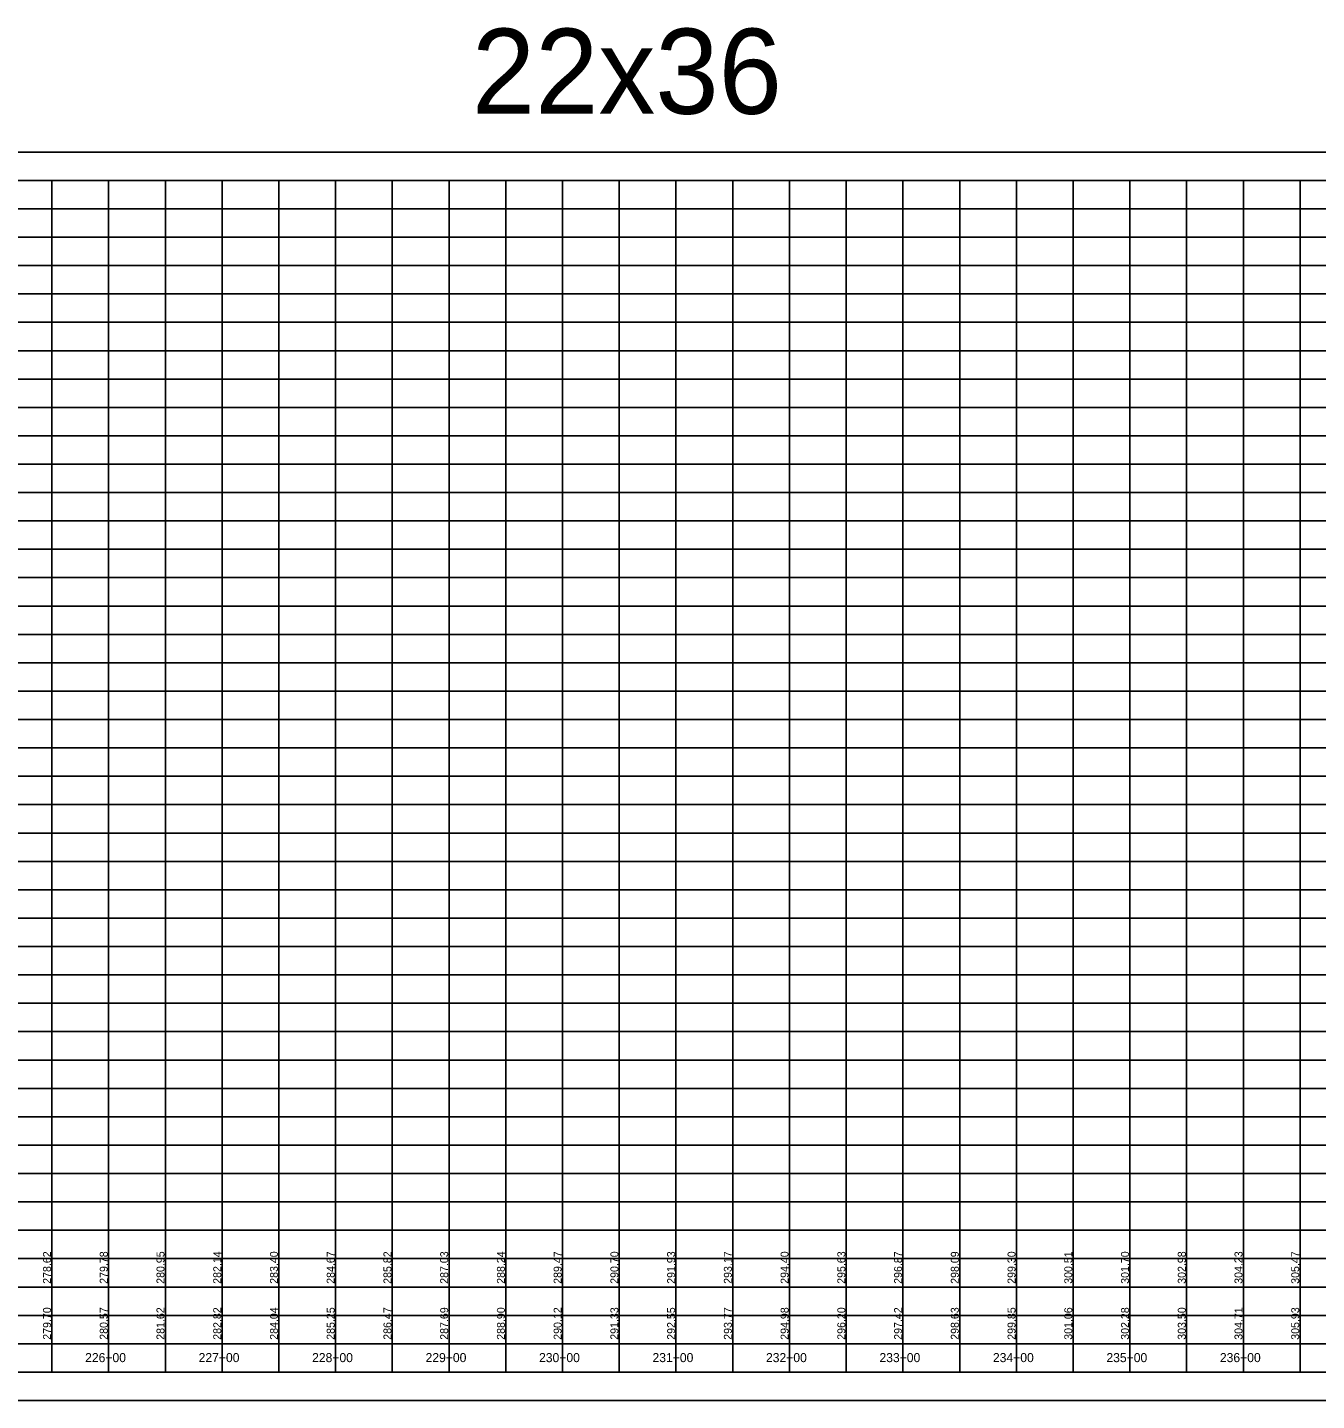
# Model space of a CAD drawing. Extents: x 1873632 to 1926512, y 813126 to 836257.
# Drawn here: x 1900891 to 1902027, y 831005 to 832214 of the extents above; entities that cross this region are included whole.
import ezdxf

# ---------------------------------------------------------------- set-up
doc = ezdxf.new("R2010")
doc.units = 0
for name, color, linetype in [('RD_DDB_StaTX', 7, 'Continuous'), ('RD_DDB_StripGrade', 7, 'Continuous'), ('RD_PD_WallFill', 7, 'Continuous'), ('RD_SHT_IplotShp', 7, 'Continuous')]:
    doc.layers.add(name, color=color, linetype=linetype)

msp = doc.modelspace()

# ---------------------------------------------------------------- linework, layer by layer
at = {"layer": 'RD_PD_WallFill'}
for p, q in [((1899712.9, 832079.6), (1905062.9, 832079.6)), ((1899712.9, 832079.6), (1901462.9, 832079.6)), ((1900912.9, 831029.6), (1900912.9, 832079.6)), ((1900912.9, 831029.6), (1900912.9, 832079.6)), ((1900962.9, 831029.6), (1900962.9, 832079.6)), ((1900962.9, 831029.6), (1900962.9, 832079.6)), ((1901012.9, 831029.6), (1901012.9, 832079.6)), ((1901012.9, 831029.6), (1901012.9, 832079.6)), ((1901062.9, 831029.6), (1901062.9, 832079.6)), ((1901062.9, 831029.6), (1901062.9, 832079.6)), ((1901112.9, 831029.6), (1901112.9, 832079.6)), ((1901112.9, 831029.6), (1901112.9, 832079.6)), ((1901162.9, 831029.6), (1901162.9, 832079.6)), ((1901162.9, 831029.6), (1901162.9, 832079.6)), ((1901212.9, 831029.6), (1901212.9, 832079.6)), ((1901212.9, 831029.6), (1901212.9, 832079.6)), ((1901262.9, 831029.6), (1901262.9, 832079.6)), ((1901262.9, 831029.6), (1901262.9, 832079.6)), ((1901312.9, 831029.6), (1901312.9, 832079.6)), ((1901312.9, 831029.6), (1901312.9, 832079.6)), ((1901362.9, 831029.6), (1901362.9, 832079.6)), ((1901362.9, 831029.6), (1901362.9, 832079.6)), ((1901412.9, 831029.6), (1901412.9, 832079.6)), ((1901412.9, 831029.6), (1901412.9, 832079.6)), ((1901462.9, 831029.6), (1901462.9, 832079.6)), ((1901462.9, 831029.6), (1901462.9, 832079.6)), ((1901512.9, 831029.6), (1901512.9, 832079.6)), ((1901512.9, 831029.6), (1901512.9, 832079.6)), ((1901562.9, 831029.6), (1901562.9, 832079.6)), ((1901562.9, 831029.6), (1901562.9, 832079.6)), ((1901612.9, 831029.6), (1901612.9, 832079.6)), ((1901612.9, 831029.6), (1901612.9, 832079.6)), ((1901662.9, 831029.6), (1901662.9, 832079.6)), ((1901662.9, 831029.6), (1901662.9, 832079.6)), ((1901712.9, 831029.6), (1901712.9, 832079.6)), ((1901712.9, 831029.6), (1901712.9, 832079.6)), ((1901762.9, 831029.6), (1901762.9, 832079.6)), ((1901762.9, 831029.6), (1901762.9, 832079.6)), ((1901812.9, 831029.6), (1901812.9, 832079.6)), ((1901812.9, 831029.6), (1901812.9, 832079.6)), ((1901862.9, 831029.6), (1901862.9, 832079.6)), ((1901862.9, 831029.6), (1901862.9, 832079.6)), ((1901912.9, 831029.6), (1901912.9, 832079.6)), ((1901912.9, 831029.6), (1901912.9, 832079.6)), ((1901962.9, 831029.6), (1901962.9, 832079.6)), ((1901962.9, 831029.6), (1901962.9, 832079.6)), ((1902012.9, 831029.6), (1902012.9, 832079.6)), ((1902012.9, 831029.6), (1902012.9, 832079.6)), ((1900162.9, 832054.6), (1905062.9, 832054.6)), ((1900162.9, 832054.6), (1905062.9, 832054.6)), ((1900162.9, 832029.6), (1905062.9, 832029.6)), ((1900162.9, 832004.6), (1905062.9, 832004.6)), ((1900162.9, 831979.6), (1905062.9, 831979.6)), ((1900162.9, 831954.6), (1905062.9, 831954.6)), ((1899712.9, 831929.6), (1905062.9, 831929.6)), ((1899712.9, 831904.6), (1905062.9, 831904.6)), ((1899712.9, 831879.6), (1905062.9, 831879.6)), ((1899712.9, 831854.6), (1905062.9, 831854.6)), ((1899712.9, 831829.6), (1905062.9, 831829.6)), ((1899712.9, 831804.6), (1905062.9, 831804.6)), ((1899712.9, 831779.6), (1905062.9, 831779.6)), ((1899712.9, 831754.6), (1905062.9, 831754.6)), ((1899712.9, 831729.6), (1905062.9, 831729.6)), ((1899712.9, 831704.6), (1905062.9, 831704.6)), ((1899712.9, 831679.6), (1905062.9, 831679.6)), ((1899712.9, 831654.6), (1905062.9, 831654.6)), ((1899712.9, 831629.6), (1905062.9, 831629.6)), ((1899712.9, 831604.6), (1905062.9, 831604.6)), ((1899712.9, 831579.6), (1905062.9, 831579.6)), ((1899712.9, 831554.6), (1905062.9, 831554.6)), ((1899712.9, 831529.6), (1905062.9, 831529.6)), ((1899712.9, 831504.6), (1905062.9, 831504.6)), ((1899712.9, 831479.6), (1905062.9, 831479.6)), ((1899712.9, 831454.6), (1905062.9, 831454.6)), ((1899712.9, 831429.6), (1905062.9, 831429.6)), ((1899712.9, 831404.6), (1905062.9, 831404.6)), ((1899712.9, 831379.6), (1905062.9, 831379.6)), ((1899712.9, 831354.6), (1905062.9, 831354.6)), ((1899712.9, 831329.6), (1905062.9, 831329.6)), ((1899712.9, 831304.6), (1905062.9, 831304.6)), ((1899712.9, 831279.6), (1905062.9, 831279.6)), ((1899712.9, 831254.6), (1905062.9, 831254.6)), ((1899712.9, 831229.6), (1905062.9, 831229.6)), ((1899712.9, 831204.6), (1905062.9, 831204.6)), ((1899712.9, 831179.6), (1905062.9, 831179.6)), ((1899712.9, 831154.6), (1905062.9, 831154.6)), ((1899712.9, 831129.6), (1905062.9, 831129.6)), ((1899712.9, 831104.6), (1905062.9, 831104.6)), ((1899712.9, 831079.6), (1905062.9, 831079.6)), ((1899712.9, 831054.6), (1905062.9, 831054.6)), ((1899712.9, 831029.6), (1905062.9, 831029.6)), ((1899712.9, 831029.6), (1905062.9, 831029.6))]:
    msp.add_line(p, q, dxfattribs=at)
at = {"layer": 'RD_SHT_IplotShp'}
msp.add_lwpolyline([(1899687.9, 831004.6), (1905087.9, 831004.6), (1905087.9, 832104.6), (1899687.9, 832104.6)], close=True, dxfattribs=at)

# ---------------------------------------------------------------- texts
at = {"layer": 'RD_DDB_StaTX'}
for s, p in [('226+00', (1900942.2, 831038.4)), ('227+00', (1901042.2, 831038.4)), ('228+00', (1901142.2, 831038.4)), ('229+00', (1901242.2, 831038.4)), ('230+00', (1901342.2, 831038.4)), ('231+00', (1901442.2, 831038.4)), ('232+00', (1901542.2, 831038.4)), ('233+00', (1901642.2, 831038.4)), ('234+00', (1901742.2, 831038.4)), ('235+00', (1901842.2, 831038.4)), ('236+00', (1901942.2, 831038.4))]:
    msp.add_text(s, height=8, dxfattribs=at).set_placement(p)
at = {"layer": 'RD_DDB_StripGrade'}
for s, p in [('278.62', (1900912.1, 831107.4)), ('279.78', (1900962.1, 831107.4)), ('280.95', (1901012.1, 831107.4)), ('282.14', (1901062.1, 831107.4)), ('283.40', (1901112.1, 831107.4)), ('284.67', (1901162.1, 831107.4)), ('285.82', (1901212.1, 831107.4)), ('287.03', (1901262.1, 831107.4)), ('288.24', (1901312.1, 831107.4)), ('289.47', (1901362.1, 831107.4)), ('290.70', (1901412.1, 831107.4)), ('291.93', (1901462.1, 831107.4)), ('293.17', (1901512.1, 831107.4)), ('294.40', (1901562.1, 831107.4)), ('295.63', (1901612.1, 831107.4)), ('296.87', (1901662.1, 831107.4)), ('298.09', (1901712.1, 831107.4)), ('299.30', (1901762.1, 831107.4)), ('300.51', (1901812.1, 831107.4)), ('301.70', (1901862.1, 831107.4)), ('302.98', (1901912.1, 831107.4)), ('304.23', (1901962.1, 831107.4)), ('305.47', (1902012.1, 831107.4)), ('279.70', (1900912.1, 831058.1)), ('280.57', (1900962.1, 831058.1)), ('281.62', (1901012.1, 831058.1)), ('282.82', (1901062.1, 831058.1)), ('284.04', (1901112.1, 831058.1)), ('285.25', (1901162.1, 831058.1)), ('286.47', (1901212.1, 831058.1)), ('287.69', (1901262.1, 831058.1)), ('288.90', (1901312.1, 831058.1)), ('290.12', (1901362.1, 831058.1)), ('291.33', (1901412.1, 831058.1)), ('292.55', (1901462.1, 831058.1)), ('293.77', (1901512.1, 831058.1)), ('294.98', (1901562.1, 831058.1)), ('296.20', (1901612.1, 831058.1)), ('297.42', (1901662.1, 831058.1)), ('298.63', (1901712.1, 831058.1)), ('299.85', (1901762.1, 831058.1)), ('301.06', (1901812.1, 831058.1)), ('302.28', (1901862.1, 831058.1)), ('303.50', (1901912.1, 831058.1)), ('304.71', (1901962.1, 831058.1)), ('305.93', (1902012.1, 831058.1))]:
    msp.add_text(s, height=7, rotation=90, dxfattribs=at).set_placement(p)
at = {"layer": 'RD_PD_WallFill'}
msp.add_text('22x36', height=75, dxfattribs=at).set_placement((1901283, 832138.3))
msp.add_text('22x36', height=75, dxfattribs=at).set_placement((1901283, 832138.3))

doc.saveas('drawing.dxf')
